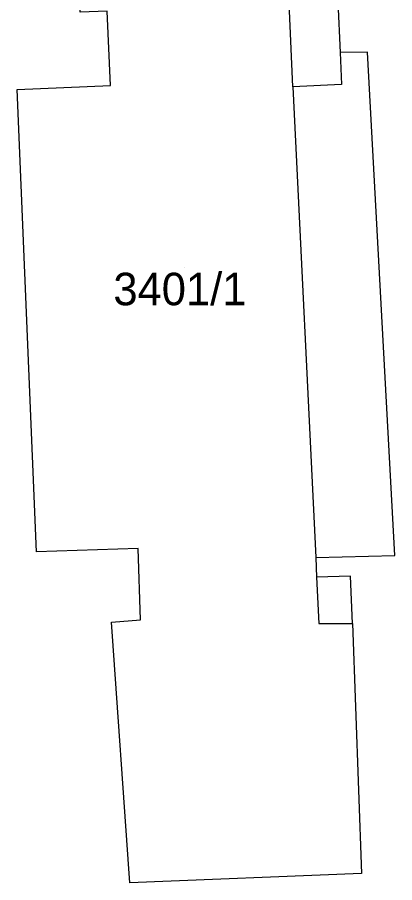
# Model space of a CAD drawing. Extents: x -264070 to -262271, y -1238894 to -1238141.
# Drawn here: x -262748.5 to -262725.3, y -1238443.5 to -1238390.2 of the extents above; entities that cross this region are included whole.
import ezdxf

# ---------------------------------------------------------------- set-up
doc = ezdxf.new("R2010")
doc.units = 0
for name, color, linetype in [('body_kn', 7, 'Continuous'), ('kladpar_druhypozemkov', 7, 'Continuous'), ('kladpar_parcelnecisla', 7, 'Continuous'), ('zappar_hrandruhpozemk', 7, 'Continuous')]:
    doc.layers.add(name, color=color, linetype=linetype)

msp = doc.modelspace()

# ---------------------------------------------------------------- linework, layer by layer
at = {"layer": 'body_kn'}
for p, q in [((-262728.66, -1238392.4), (-262728.66, -1238392.4)), ((-262726.97, -1238392.38), (-262726.97, -1238392.38)), ((-262742.78, -1238394.44), (-262742.78, -1238394.44)), ((-262731.57, -1238394.51), (-262731.57, -1238394.51)), ((-262728.57, -1238394.38), (-262728.57, -1238394.38)), ((-262748.5, -1238394.68), (-262748.5, -1238394.68)), ((-262747.32, -1238423.12), (-262747.32, -1238423.12)), ((-262747.32, -1238423.12), (-262747.32, -1238423.12)), ((-262741.08, -1238422.91), (-262741.08, -1238422.91)), ((-262730.15, -1238423.47), (-262730.15, -1238423.47)), ((-262725.3, -1238423.34), (-262725.3, -1238423.34)), ((-262730.1, -1238424.68), (-262730.1, -1238424.68)), ((-262730.1, -1238424.68), (-262730.1, -1238424.68)), ((-262728.02, -1238424.61), (-262728.02, -1238424.61)), ((-262742.7, -1238427.44), (-262742.7, -1238427.44)), ((-262740.93, -1238427.31), (-262740.93, -1238427.31)), ((-262729.96, -1238427.52), (-262729.96, -1238427.52)), ((-262727.9, -1238427.52), (-262727.9, -1238427.52)), ((-262727.9, -1238427.52), (-262727.9, -1238427.52)), ((-262727.34, -1238442.9), (-262727.34, -1238442.9)), ((-262741.59, -1238443.47), (-262741.59, -1238443.47))]:
    msp.add_line(p, q, dxfattribs=at)
at = {"layer": 'kladpar_druhypozemkov'}
msp.add_line((-262738.23, -1238405.65), (-262738.23, -1238405.65), dxfattribs=at)
at = {"layer": 'zappar_hrandruhpozemk'}
for p, q in [((-262731.57, -1238394.51), (-262731.78, -1238389.37)), ((-262726.97, -1238392.38), (-262728.66, -1238392.4)), ((-262725.3, -1238423.34), (-262726.97, -1238392.38)), ((-262731.57, -1238394.51), (-262730.15, -1238423.47)), ((-262747.32, -1238423.12), (-262748.5, -1238394.68)), ((-262730.15, -1238423.47), (-262725.3, -1238423.34)), ((-262730.15, -1238423.47), (-262730.1, -1238424.68)), ((-262730.1, -1238424.68), (-262729.96, -1238427.52))]:
    msp.add_line(p, q, dxfattribs=at)
for points in [[(-262748.5, -1238394.68), (-262742.78, -1238394.44), (-262742.97, -1238389.85), (-262744.63, -1238389.92), (-262745.22, -1238375.9)], [(-262728.79, -1238389.28), (-262728.66, -1238392.4), (-262728.57, -1238394.38), (-262731.57, -1238394.51)], [(-262729.96, -1238427.52), (-262727.9, -1238427.52), (-262727.34, -1238442.9), (-262741.59, -1238443.47), (-262742.7, -1238427.44), (-262740.93, -1238427.31), (-262741.08, -1238422.91), (-262747.32, -1238423.12)], [(-262727.9, -1238427.52), (-262728.02, -1238424.61), (-262730.1, -1238424.68)]]:
    msp.add_lwpolyline(points, dxfattribs=at)

# ---------------------------------------------------------------- texts
at = {"layer": 'kladpar_parcelnecisla'}
msp.add_text('3401/1', height=2, dxfattribs=at).set_placement((-262742.595, -1238407.95))

doc.saveas('drawing.dxf')
